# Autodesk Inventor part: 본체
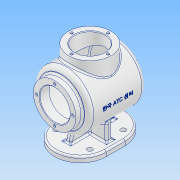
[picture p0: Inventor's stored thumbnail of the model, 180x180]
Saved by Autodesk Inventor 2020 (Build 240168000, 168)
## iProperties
Created: 2023-01
Part Number: 본체
Material: 알루미늄 6061
Document SubType Name: Modeling
Designer: user
Density: 2.7 g/cm^3
Appearance: 알루미늄 - 평지
Author: user
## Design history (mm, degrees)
sketch "스케치3"
  geometry: L1 (46, -63)-(-46, -63); L2 (-46, -63)-(-46, 63); L3 (-46, 63)-(46, 63); L4 (46, 63)-(46, -63); L5 (46, -63)-(-46, 63); L6 (-46, -63)-(46, 63); 1 further point
  constraints: 12 end point, 2 midpoint, 2 parallel, 1 horizontal, 1 perpendicular
  dimensions: "d3" = 92 distance of L2.end L3.end; "d4" = 126 distance of L1.end L2.end
extrude "돌출1" new body sketch "스케치3" distance "d5" = 10; taper "d6" = 0 deg
fillet "모깎기1" dims "d7" = 46
fillet "모깎기2" dims "d8" = 46
sketch "스케치4"
  geometry: L1 (0, 0)-(30, 0); L2 (30, 0)-(30, -30); L3 (30, -30)-(0, -30); L4 (0, -30)-(0, 0); C1 r 4.5 at (30, -30)
  constraints: 8 end point, 2 parallel, 1 centre point, 1 coincident, 1 horizontal, 1 perpendicular
  dimensions: "d9" = 30 distance of L2.end L3.end; "d10" = 30 distance of L1.end L2.end; "d11" = 9 diameter of C1
extrude "돌출2" cut sketch "스케치4" extent not by distance; stored distance "d12" = 0; taper "d13" = 0 deg
sketch "스케치5"
  geometry: L1 (0, 0)-(-30, 0); L2 (-30, 0)-(-30, -30); L3 (-30, -30)-(0, -30); L4 (0, -30)-(0, 0); C1 r 4.5 at (-30, -30)
  constraints: 8 end point, 2 parallel, 1 centre point, 1 coincident, 1 horizontal, 1 perpendicular
  dimensions: "d14" = 30 distance of L3.end L2.end; "d15" = 30 distance of L2.end L1.end; "d16" = 9 diameter of C1
extrude "돌출3" cut sketch "스케치5" extent not by distance; stored distance "d17" = 0; taper "d18" = 0 deg
sketch "스케치6"
  geometry: L1 (0, 0)-(-30, 0); L2 (-30, 0)-(-30, 30); L3 (-30, 30)-(0, 30); L4 (0, 30)-(0, 0); L5 (0, 0)-(30, 0); L6 (30, 0)-(30, 30); L7 (30, 30)-(0, 30); L8 (0, 30)-(0, 0); C1 r 4.5 at (-30, 30); C2 r 4.5 at (30, 30)
  constraints: 16 end point, 4 parallel, 2 centre point, 2 coincident, 2 horizontal, 2 perpendicular
  dimensions: "d19" = 30 distance of L2.end L3.end; "d20" = 30 distance of L1.end L2.end; "d21" = 30 distance of L7.end L6.end; "d22" = 30 distance of L6.end L5.end; "d23" = 9 diameter of C1; "d24" = 9 diameter of C2
extrude "돌출4" cut sketch "스케치6" extent not by distance; stored distance "d25" = 0; taper "d26" = 0 deg
sketch "스케치7"
  geometry: L1 (0, 0)-(80, 0); L2 (80, 0)-(80, 63); L3 (80, 63)-(118, 63); L4 (118, 63)-(118, 51); L5 (118, 51)-(80, 51)
  constraints: 10 end point, 3 perpendicular, 2 horizontal, 1 point on line
  dimensions: "d27" = 80 distance of L1.start L1.end; "d28" = 63 distance of L1.end L2.end; "d29" = 38 distance of L2.end L3.end; "d30" = 12 distance of L3.end L4.end
revolve "회전1" sketch "스케치7" stored, may be unused: angle "d31" = 90 deg
sketch "스케치8"
  geometry: L1 (42, 63)-(118, 63) reference; L2 (42, 51)-(118, 51) reference; L3 (80, 51)-(130, 51); L4 (130, 51)-(130, -48.283); L5 (80, 51)-(80, -59); A1 r 122 centre (80, 63) between (130, -48.283) and (80, -59); 2 further points
  constraints: 6 end point, 2 midpoint, 2 point on circle, 1 centre point, 1 parallel, 1 perpendicular, 1 point on line
  dimensions: "d32" = 244 diameter of A1; "d33" = 50 distance of L3.start L3.end
revolve "회전2" sketch "스케치8" stored, may be unused: angle "d34" = 90 deg
sketch "스케치9"
  geometry: L1 (0, 0)-(144, 0); L2 (144, 0)-(144, 38); L3 (144, 38)-(94.086, 38); L4 (94.086, 38)-(94.086, 0)
  constraints: 8 end point, 3 perpendicular, 1 horizontal, 1 point on line
  dimensions: "d35" = 144 distance of L1.start L1.end; "d36" = 38 distance of L1.end L2.end
revolve "회전3" sketch "스케치9" stored, may be unused: angle "d37" = 90 deg
sketch "스케치10"
  geometry: L1 (50, -51)-(-50, -51) reference; L2 (35, 0)-(35, 5); L3 (35, 5)-(-35, 5); L4 (-35, 5)-(-35, -5); L5 (-35, -5)-(35, -5); L6 (35, -5)-(35, 0); 1 further point
  constraints: 10 end point, 1 perpendicular, 1 point on line, 1 vertical
extrude "돌출5" join sketch "스케치10" distance "d43" = 64.5; taper "d44" = 0 deg
sketch "스케치11"
  geometry: L1 (10, 63)-(10, 17) reference; L2 (10, 63)-(10, 40); L3 (10, 40)-(45.674, 30.441); L4 (45.674, 30.441)-(45.674, 0); L5 (45.674, 0)-(4.837, 0); L6 (4.837, 0)-(4.837, 40); L7 (4.837, 40)-(10, 40); 1 further point
  constraints: 12 end point, 3 perpendicular, 1 midpoint, 1 parallel
  dimensions: "d45" = 23 distance of L1.start L2.end; "d46" = 105 deg angle of L3 L2
extrude "돌출6" join sketch "스케치11" stored distance "d47" = 10; taper "d48" = 0 deg
sketch "스케치12"
  geometry: L1 (10, 63)-(10, 17) reference; L2 (10, 17)-(10, -17) reference; L3 (10, 63)-(10, -40); L4 (10, -17)-(10, -63) reference; L5 (10, -40)-(53.269, -28.406); L6 (10, -40)-(54.795, -40); L7 (53.269, -28.406)-(53.269, 0); L8 (53.269, 0)-(5.759, 0); L9 (5.759, 0)-(5.759, -40); L10 (5.759, -40)-(10, -40); 3 further points
  constraints: 14 end point, 3 perpendicular, 1 equal length, 1 horizontal, 1 midpoint, 1 vertical
  dimensions: "d49" = 103 distance of L1.start L3.end (derived); "d51" = 15 deg angle of L6 L5
extrude "돌출7" join sketch "스케치12" stored distance "d52" = 10; taper "d53" = 0 deg
sketch "스케치13"
  geometry: C1 r 38 at (0, 0) reference; C2 r 27 at (0, 0); 1 further point
  constraints: 1 centre point, 1 coincident
  dimensions: "d54" = 54 diameter of C2
extrude "돌출8" cut sketch "스케치13" distance "d55" = 17; taper "d56" = 0 deg
sketch "스케치15"
  geometry: L1 (53, 46)-(107, 46) reference; L2 (80, 46)-(125, 46); L3 (125, 46)-(125, -43.303); L4 (80, 46)-(80, -54); A1 r 100 centre (80, 46) between (80, -54) and (125, -43.303); 3 further points
  constraints: 6 end point, 2 point on circle, 1 centre point, 1 coincident, 1 horizontal, 1 midpoint, 1 vertical
revolve "회전4" sketch "스케치15" stored, may be unused: angle "d59" = 90 deg
sketch "스케치16"
  geometry: C1 r 38 at (0, 0) reference; C2 r 27 at (0, 0)
  constraints: 1 centre point, 1 coincident
  dimensions: "d60" = 54 diameter of C2
extrude "돌출9" cut sketch "스케치16" distance "d61" = 66.75; taper "d62" = 0 deg
sketch "스케치17" dims "d63" = 65
  geometry: L1 (0, 0)-(0, 32.5); C1 r 38 at (0, 0) reference; 1 further point
  constraints: 2 end point, 1 coincident, 1 vertical alignment, 2 other
hole "구멍1" sketch "스케치17" at (0, 32.5) diameter "d64" = 3.242; stored, may be unused: countersink angle "d68" = 90 deg, drill point angle "d70" = 118 deg; dims "d65" = 8, "d66" = 5, "d67" = 4.775, "d69" = 10
sketch "스케치19" dims "d74" = 65
  geometry: L1 (0, 0)-(0, 32.5); C1 r 38 at (0, 0) reference
  constraints: 2 end point, 1 coincident, 1 vertical alignment, 2 other
hole "구멍2" sketch "스케치19" at (0, 32.5) diameter "d75" = 3.242; stored, may be unused: countersink angle "d79" = 90 deg, drill point angle "d81" = 118 deg; dims "d76" = 8, "d77" = 5, "d78" = 4.775, "d80" = 10
chamfer "모따기1" distance "d85" = 1; stored, may be unused: second distance "d86" = 2, angle "d87" = 45 deg
fillet "모깎기3" dims "d88" = 3
fillet "모깎기4" dims "d89" = 8
fillet "모깎기5" dims "d90" = 3
fillet "모깎기6" dims "d91" = 3
fillet "모깎기7" dims "d92" = 3
fillet "모깎기8" dims "d93" = 3
fillet "모깎기9" dims "d94" = 3
fillet "모깎기10" dims "d95" = 3
fillet "모깎기11" dims "d96" = 3
node "작업 평면1"
sketch "스케치20"
  geometry: L1 (3, 26.07)-(3, -28.787); L2 (3, -28.787)-(-3, -28.787); L3 (-3, -28.787)-(-3, 26.07); L4 (-3, 26.07)-(3, 26.07); L5 (-38, 61.642)-(38, 61.642) reference; L6 (50, 41.642)-(-50, 41.642) reference; 3 further points
  constraints: 2 midpoint, 2 other
  dimensions: "d102" = 6 distance of point (-3, -1.358) point (3, -1.358); "d103" = 63 distance from line of L5 point (-3, -1.358); "d104" = 77 distance of point (-80, -1.358) point (-3, -1.358)
feature "엠보싱1" sketch "스케치20" dims "d9" = 30, "d10" = 30, "d11" = 9, "d105" = 0.5, "d106" = 0
node "솔리드1"
pattern_circular "원형 패턴1" dims angle "d72" = 360 deg
pattern_circular "원형 패턴2" dims angle "d83" = 360 deg
feature "A9D066F2-1C7D-4E18-AEED-F7BC21143FA4" dims "d64" = 3.242, "d65" = 8, "d66" = 5, "d67" = 4.775, "d68" = 90 deg, "d69" = 10, "d70" = 118 deg
